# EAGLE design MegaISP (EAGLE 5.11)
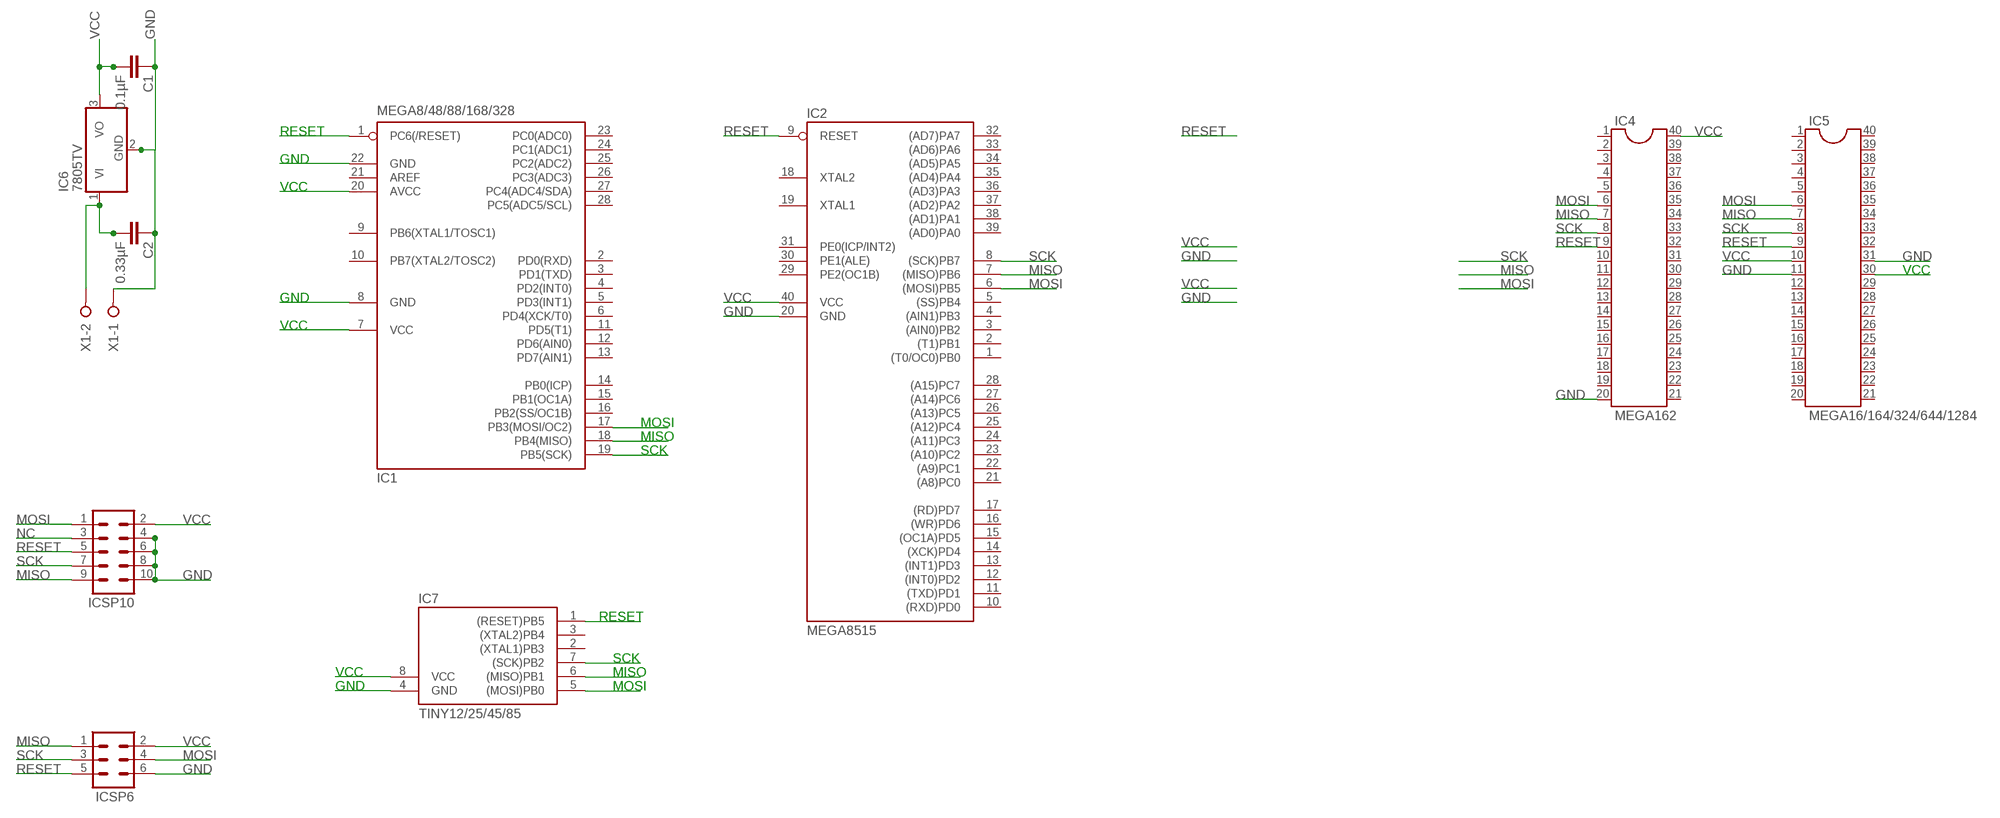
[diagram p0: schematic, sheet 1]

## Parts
C1  0.1µF  C-EU025-024X044  [C025-024X044]
C2  0.33µF  C-EU025-024X044  [C025-024X044]
IC1  MEGA8/48/88/168/328  MEGA8-P  [DIL28-3]
IC2  MEGA8515  MEGA8515-P  [DIL40]
IC4  MEGA162  DIL40  [DIL40]
IC5  MEGA16/164/324/644/1284  DIL40  [DIL40]
IC6  7805TV  [TO220V]
IC7  TINY12/25/45/85  TINY12P  [DIL08]
ICSP6  ML6  [ML6]
ICSP10  ML10  [ML10]
X1  W237-2N  [W237-2N]

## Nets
GND: C1.1 C2.1 IC1.8(GND) IC1.22(GND) IC2.20(GND) IC4.20 IC5.11 IC5.31 IC6.2(GND) IC7.4(GND) ICSP6.6 ICSP10.4 ICSP10.6 ICSP10.8 ICSP10.10 X1.1
MISO: IC1.18(PB4(MISO)) IC2.7((MISO)PB6) IC4.7 IC5.7 IC7.6((MISO)PB1) ICSP6.1 ICSP10.9
MOSI: IC1.17(PB3(MOSI/OC2)) IC2.6((MOSI)PB5) IC4.6 IC5.6 IC7.5((MOSI)PB0) ICSP6.4 ICSP10.1
N$2: C2.2 IC6.1(VI) X1.2
NC: ICSP10.3
RESET: IC1.1(PC6(/RESET)) IC2.9(RESET) IC4.9 IC5.9 IC7.1((RESET)PB5) ICSP6.5 ICSP10.5
SCK: IC1.19(PB5(SCK)) IC2.8((SCK)PB7) IC4.8 IC5.8 IC7.7((SCK)PB2) ICSP6.3 ICSP10.7
VCC: C1.2 IC1.7(VCC) IC1.20(AVCC) IC2.40(VCC) IC4.40 IC5.10 IC5.30 IC6.3(VO) IC7.8(VCC) ICSP6.2 ICSP10.2
Unconnected: IC1.2(PD0(RXD)) IC1.3(PD1(TXD)) IC1.4(PD2(INT0)) IC1.5(PD3(INT1)) IC1.6(PD4(XCK/T0)) IC1.9(PB6(XTAL1/TOSC1)) IC1.10(PB7(XTAL2/TOSC2)) IC1.11(PD5(T1)) IC1.12(PD6(AIN0)) IC1.13(PD7(AIN1)) IC1.14(PB0(ICP)) IC1.15(PB1(OC1A)) IC1.16(PB2(SS/OC1B)) IC1.21(AREF) IC1.23(PC0(ADC0)) IC1.24(PC1(ADC1)) IC1.25(PC2(ADC2)) IC1.26(PC3(ADC3)) IC1.27(PC4(ADC4/SDA)) IC1.28(PC5(ADC5/SCL)) IC2.1((T0/OC0)PB0) IC2.2((T1)PB1) IC2.3((AIN0)PB2) IC2.4((AIN1)PB3) IC2.5((SS)PB4) IC2.10((RXD)PD0) IC2.11((TXD)PD1) IC2.12((INT0)PD2) IC2.13((INT1)PD3) IC2.14((XCK)PD4) IC2.15((OC1A)PD5) IC2.16((WR)PD6) IC2.17((RD)PD7) IC2.18(XTAL2) IC2.19(XTAL1) IC2.21((A8)PC0) IC2.22((A9)PC1) IC2.23((A10)PC2) IC2.24((A11)PC3) IC2.25((A12)PC4) IC2.26((A13)PC5) IC2.27((A14)PC6) IC2.28((A15)PC7) IC2.29(PE2(OC1B)) IC2.30(PE1(ALE)) IC2.31(PE0(ICP/INT2)) IC2.32((AD7)PA7) IC2.33((AD6)PA6) IC2.34((AD5)PA5) IC2.35((AD4)PA4) IC2.36((AD3)PA3) IC2.37((AD2)PA2) IC2.38((AD1)PA1) IC2.39((AD0)PA0) IC4.1 IC4.2 IC4.3 IC4.4 IC4.5 IC4.10 IC4.11 IC4.12 IC4.13 IC4.14 IC4.15 IC4.16 IC4.17 IC4.18 IC4.19 IC4.21 IC4.22 IC4.23 IC4.24 IC4.25 IC4.26 IC4.27 IC4.28 IC4.29 IC4.30 IC4.31 IC4.32 IC4.33 IC4.34 IC4.35 IC4.36 IC4.37 IC4.38 IC4.39 IC5.1 IC5.2 IC5.3 IC5.4 IC5.5 IC5.12 IC5.13 IC5.14 IC5.15 IC5.16 IC5.17 IC5.18 IC5.19 IC5.20 IC5.21 IC5.22 IC5.23 IC5.24 IC5.25 IC5.26 IC5.27 IC5.28 IC5.29 IC5.32 IC5.33 IC5.34 IC5.35 IC5.36 IC5.37 IC5.38 IC5.39 IC5.40 IC7.2((XTAL1)PB3) IC7.3((XTAL2)PB4)

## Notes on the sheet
- RESET
- GND
- VCC
- VCC
- GND
- VCC
- MOSI
- MISO
- SCK
- RESET
- SCK
- VCC | MISO
- GND | MOSI

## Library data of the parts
C1 C2 = resistor:C-EU: CAPACITOR, European symbol
IC1 = atmel:MEGA8-P: MICROCONTROLLER 8 Kbytes FLASH, 1 kbytes SRAM, 512 bytes EEPROM, USART, 4-channel 10 bit ADC, 2-channel 8 bit ADC Pin compatible with Atmega48, ATMega88, ATMega168 Source: avr.lbr; OC_FARNELL: unknown; OC_NEWARK: unknown
IC2 = atmel:MEGA8515-P: MICROCONTROLLER 8 Kbytes FLASH 512 bytes SRAM 512 bytes EEPROM USART 8-channel 10 bit ADC Source: avr.lbr; MPN: ATMEGA8515-16PU; OC_FARNELL: 9171401; OC_NEWARK: 01M6905
IC4 IC5 = ic-package:DIL40: Dual In Line
IC6 = linear:78*: Positive VOLTAGE REGULATOR Source: http://cache.national.com/ds/LM/LM78L05.pdf http://www.fairchildsemi.com/ds/LM/LM7805.pdf
IC7 = atmel:TINY12*: MICROCONTROLLER 1 Kbytes FLASH 64 bytes EEPROM; OC_FARNELL: unknown; OC_NEWARK: unknown
ICSP6 = con-harting-ml:ML6: HARTING; OC_FARNELL: unknown; OC_NEWARK: unknown
ICSP10 = con-harting-ml:ML10: HARTING; OC_FARNELL: unknown; OC_NEWARK: unknown
X1 = con-wago-508:W237-2N: WAGO SREW CLAMP; OC_FARNELL: unknown; OC_NEWARK: unknown

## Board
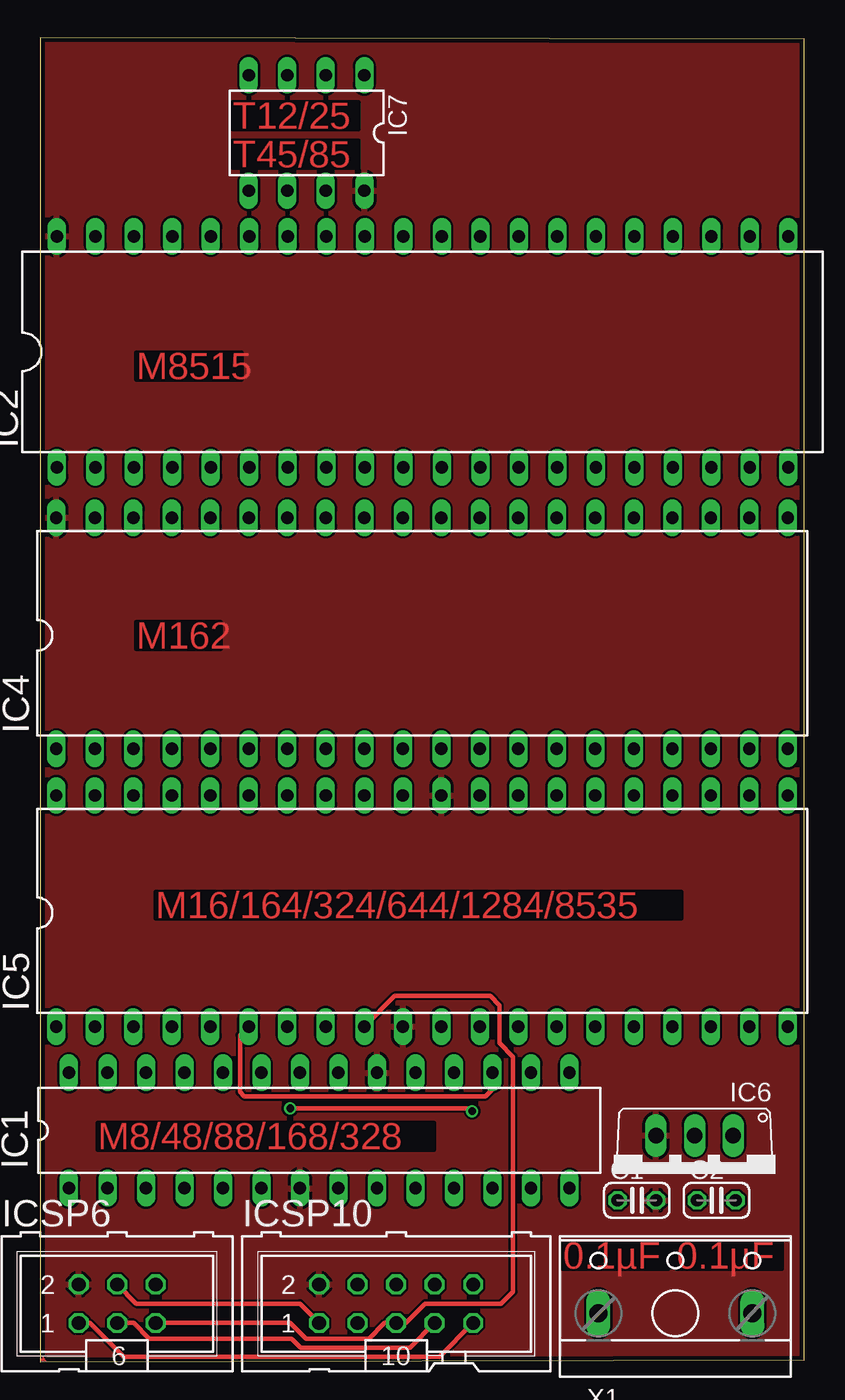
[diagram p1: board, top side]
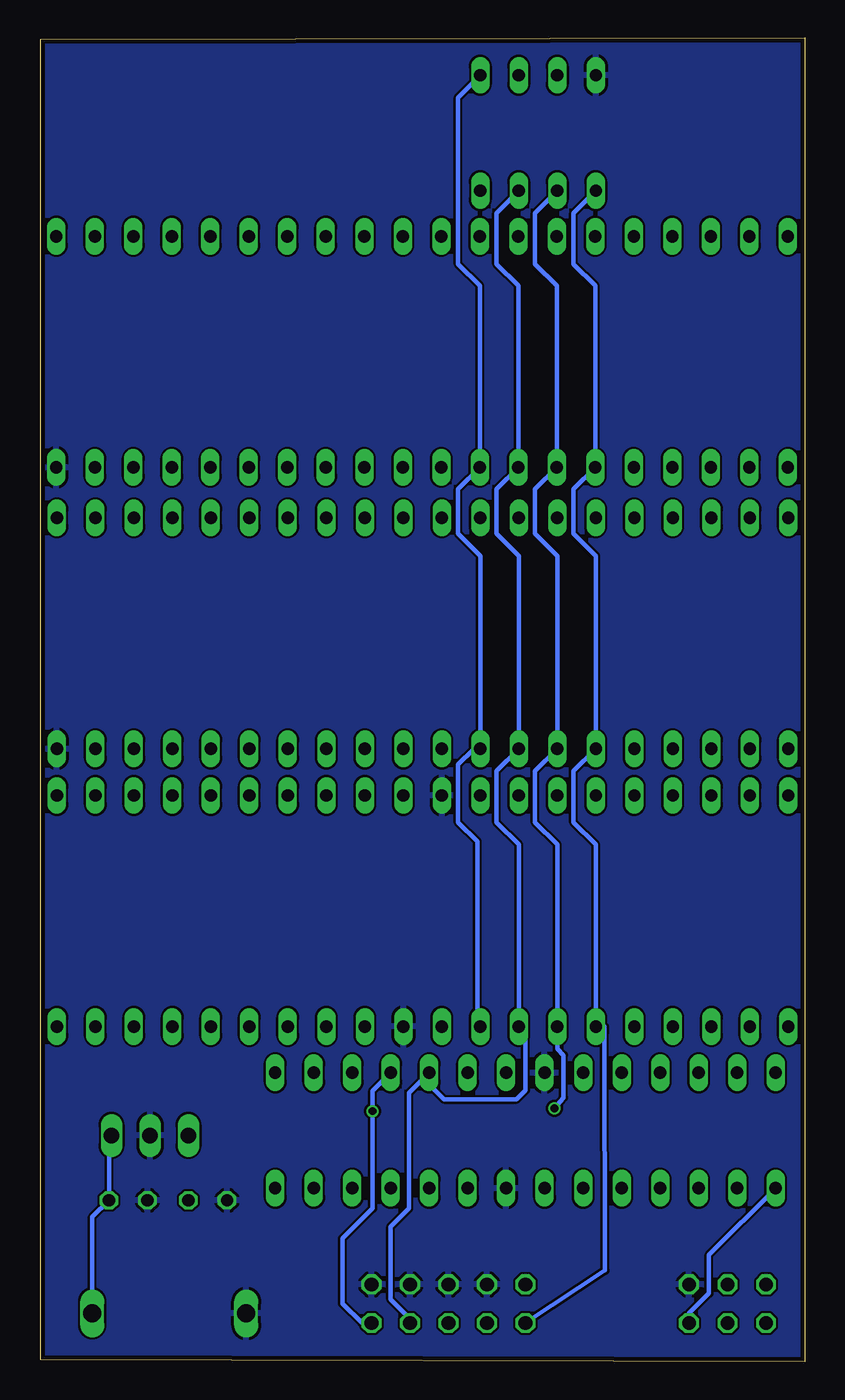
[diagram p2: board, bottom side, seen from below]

Size 50.4 x 87.3 mm. Coordinates in mm from the lower left corner, seen from the top.
Outline: 0,0 50.4,0.1 50.4,87.2 0,87.3 0,0
Copper layers (1*16): Top 0.035mm / dielectric 1.5mm / Bottom 0.035mm
Design rules "PCB-POOL Standard": minimum track width 0.15mm, minimum drill 0.3mm, track to track 0.15mm, track to pad 0.15mm, pad to pad 0.15mm, via to via 0.15mm, smd to smd 0.15mm, copper to edge 0.3mm, drill to drill 0.2mm, minimum pad ring 0.2mm, minimum via ring 0.15mm, stop-mask expansion 0.075mm, vias tented up to drill 0mil, thermal gap 0.2mm

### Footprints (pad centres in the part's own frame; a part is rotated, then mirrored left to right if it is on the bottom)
C025-024X044 = drill 0.813 octagon: 1 -1.27,0; 2 1.27,0
DIL28-3 = drill 0.813 long: 1 -16.51,-3.81; 2 -13.97,-3.81; 3 -11.43,-3.81; 4 -8.89,-3.81; 5 -6.35,-3.81; 6 -3.81,-3.81; 7 -1.27,-3.81; 8 1.27,-3.81; 9 3.81,-3.81; 10 6.35,-3.81; 11 8.89,-3.81; 12 11.43,-3.81; 13 13.97,-3.81; 14 16.51,-3.81; 15 16.51,3.81; 16 13.97,3.81; 17 11.43,3.81; 18 8.89,3.81; 19 6.35,3.81; 20 3.81,3.81; 21 1.27,3.81; 22 -1.27,3.81; 23 -3.81,3.81; 24 -6.35,3.81; 25 -8.89,3.81; 26 -11.43,3.81; 27 -13.97,3.81; 28 -16.51,3.81
DIL40 = drill 0.813 long: 1 -24.13,-7.62; 2 -21.59,-7.62; 3 -19.05,-7.62; 4 -16.51,-7.62; 5 -13.97,-7.62; 6 -11.43,-7.62; 7 -8.89,-7.62; 8 -6.35,-7.62; 9 -3.81,-7.62; 10 -1.27,-7.62; 11 1.27,-7.62; 12 3.81,-7.62; 13 6.35,-7.62; 14 8.89,-7.62; 15 11.43,-7.62; 16 13.97,-7.62; 17 16.51,-7.62; 18 19.05,-7.62; 19 21.59,-7.62; 20 24.13,-7.62; 21 24.13,7.62; 22 21.59,7.62; 23 19.05,7.62; 24 16.51,7.62; 25 13.97,7.62; 26 11.43,7.62; 27 8.89,7.62; 28 6.35,7.62; 29 3.81,7.62; 30 1.27,7.62; 31 -1.27,7.62; 32 -3.81,7.62; 33 -6.35,7.62; 34 -8.89,7.62; 35 -11.43,7.62; 36 -13.97,7.62; 37 -16.51,7.62; 38 -19.05,7.62; 39 -21.59,7.62; 40 -24.13,7.62
TO220V = drill 1.016 long: 1 -2.54,-2.54; 2 0,-2.54; 3 2.54,-2.54
DIL08 = drill 0.813 long: 1 -3.81,-3.81; 2 -1.27,-3.81; 3 1.27,-3.81; 4 3.81,-3.81; 5 3.81,3.81; 6 1.27,3.81; 7 -1.27,3.81; 8 -3.81,3.81
ML6 = drill 0.914 octagon: 1 -2.54,-1.27; 2 -2.54,1.27; 3 0,-1.27; 4 0,1.27; 5 2.54,-1.27; 6 2.54,1.27
ML10 = drill 0.914 octagon: 1 -5.08,-1.27; 2 -5.08,1.27; 3 -2.54,-1.27; 4 -2.54,1.27; 5 0,-1.27; 6 0,1.27; 7 2.54,-1.27; 8 2.54,1.27; 9 5.08,-1.27; 10 5.08,1.27
W237-2N = drill 1.194 long: 1 -5.08,-0.635; 2 5.08,-0.635

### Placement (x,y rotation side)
C1  39.37,10.63 0 top
C2  44.62,10.63 0 top
IC1  18.41,15.24 0 top
IC2  25.23,66.59 0 top
IC4  25.2,48.03 0 top
IC5  25.2,29.71 0 top
IC6  43.18,12.37 180 top
IC7  17.58,81.03 180 top
ICSP6  5.08,3.81 0 top
ICSP10  23.5,3.81 0 top
X1  41.91,3.81 0 top

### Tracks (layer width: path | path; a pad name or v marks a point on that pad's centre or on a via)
GND
  pour Bottom: -2.54,-2.54 53.34,-2.54 53.34,87.63 -2.54,87.63
MISO  (via drill 0.5)
  Top 0.305: ICSP6.1 3.26,2.54 5.5,0.3 26.34,0.3 ICSP10.9 | v16.5,16.7 28.21,16.7 v28.5,16.51
  Bottom 0.305: ICSP10.9 29.21,2.54 30.48,3.81 30.48,8.12 28.5,10.1 v28.5,16.51 28.5,17.86 IC1.18 | v16.5,16.7 15.9,17.4 15.9,20.2 16.31,20.61 IC5.7 16.31,34.09 17.78,35.56 17.78,38.94 IC4.7 16.31,53.14 17.78,54.61 17.78,57.54 IC2.7 16.34,70.95 17.78,72.39 17.78,75.75 IC7.6
MOSI
  Top 0.305: ICSP6.4 6.35,3.81 17.14,3.81 ICSP10.1 | IC1.17 29.84,17.95 29.4,17.5 13.47,17.5 13.19,17.78 13.19,21.52 IC5.6
  Bottom 0.305: ICSP10.1 13.17,6.01 13.2,21.7 13.2,22.09 IC5.6 13.77,34.09 15.24,35.56 15.24,38.94 IC4.6 13.77,53.14 15.24,54.61 15.24,57.54 IC2.6 13.8,70.95 15.24,72.39 15.24,75.75 IC7.5
N$2
  Bottom 0.305: X1.2 46.99,9.53 C2.2 45.89,14.74 IC6.1
RESET
  Top 0.305: ICSP6.5 16.51,2.54 17.55,1.5 21.7,1.5 22.74,2.54 ICSP10.5 24.13,2.54 25.4,3.81 30.41,3.81 31.2,4.6 31.2,20.1 30.3,21 30.3,23.5 29.7,24.1 23.39,24.1 IC5.9
  Bottom 0.305: ICSP6.5 7.62,3.18 6.3,4.5 6.3,7.04 IC1.1 | IC5.9 21.59,22.3 21.59,34.29 22.86,35.56 22.86,39.37 21.82,40.41 IC4.9 21.39,53.14 22.86,54.61 22.86,57.54 IC2.9 21.43,70.95 22.86,72.39 22.86,83.37 IC7.1
SCK
  Top 0.305: ICSP6.3 6.16,2.54 7.2,1.5 16.6,1.5 17.2,0.9 24.39,0.9 ICSP10.7
  Bottom 0.305: ICSP10.7 26.04,2.83 27.3,4.1 27.3,8.9 26.1,10.1 26.1,17.71 IC1.19 24.77,18.27 23.8,17.3 19,17.3 18.4,17.9 18.4,21.64 IC5.8 18.85,34.09 20.32,35.56 20.32,38.94 IC4.8 18.85,53.14 20.32,54.61 20.32,57.54 IC2.8 18.89,70.95 20.32,72.39 20.32,75.75 IC7.7
VCC
  pour Top: -2.54,87.63 53.34,87.63 53.34,-2.54 -2.54,-2.54
(copper drawn outside any net)
  shapes: Top area x37500

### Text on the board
Top: T12/25 | T45/85 | M8515 | M162 | M16/164/324/644/1284/8535 | M8/48/88/168/328 | 0.1µF | 0.1µF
